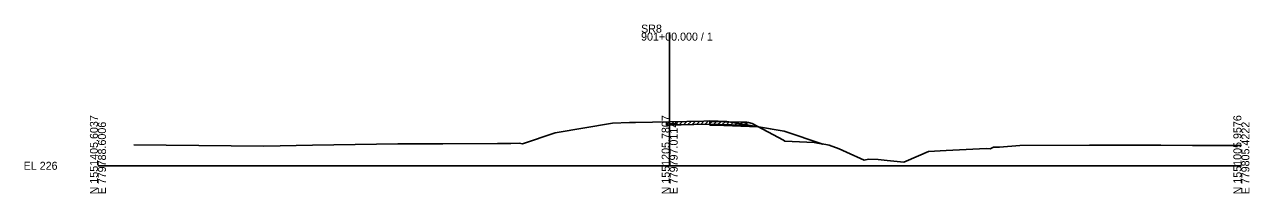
# Model space of a CAD drawing. Extents: x -26 to 787523, y -10 to 1545496.
# Drawn here: x -25.7 to 402.8, y 6990.3 to 7049.4 of the extents above; entities that cross this region are included whole.
import ezdxf

# ---------------------------------------------------------------- set-up
doc = ezdxf.new("R2010")
doc.units = 0
for name, color, linetype in [('50', 7, 'Continuous'), ('XS_CELL', 7, 'Continuous'), ('XS_M_SHAPES_EARTHWORK', 7, 'Continuous'), ('XS_P_FINISHED_GRADE', 7, 'Continuous'), ('XS_P_SUBGRADE_GRANULAR', 7, 'Continuous'), ('XS_X_GROUND', 7, 'Continuous')]:
    doc.layers.add(name, color=color, linetype=linetype)

msp = doc.modelspace()

# ---------------------------------------------------------------- linework, layer by layer
at = {"layer": '50'}
for p, q in [((198.85, 7014.25), (199.87, 7015.27)), ((198.85, 7014.25), (198.85, 7015.25)), ((200.36, 7014.28), (201.38, 7015.3)), ((201.86, 7014.31), (202.88, 7015.33)), ((203.36, 7014.34), (204.38, 7015.36)), ((204.86, 7014.37), (205.88, 7015.39)), ((206.36, 7014.4), (207.38, 7015.42)), ((207.87, 7014.43), (208.89, 7015.45)), ((209.37, 7014.46), (210.39, 7015.48)), ((210.87, 7014.49), (211.89, 7015.51)), ((212.37, 7014.51), (213.37, 7015.51)), ((213.87, 7014.5), (214.85, 7015.48)), ((215.38, 7014.47), (216.36, 7015.45)), ((216.88, 7014.44), (217.86, 7015.42)), ((218.38, 7014.4), (219.36, 7015.38)), ((219.88, 7014.37), (220.86, 7015.35)), ((221.38, 7014.34), (222.36, 7015.32)), ((222.89, 7014.31), (223.87, 7015.28)), ((224.39, 7014.27), (225.37, 7015.25)), ((225.89, 7014.24), (226.87, 7015.22)), ((227.04, 7015.21), (227.04, 7014.21)), ((198.85, 7014.25), (200, 7014.27)), ((200, 7014.27), (204, 7014.35)), ((204, 7014.35), (212.87, 7014.52)), ((212.87, 7014.52), (224.99, 7014.26)), ((224.99, 7014.26), (227.04, 7014.21))]:
    msp.add_line(p, q, dxfattribs=at)
at = {"layer": 'XS_CELL'}
for p, q in [((200, 7000), (200, 7046.57)), ((0, 7000), (200, 7000)), ((200, 7000), (400, 7000))]:
    msp.add_line(p, q, dxfattribs=at)
at = {"layer": 'XS_M_SHAPES_EARTHWORK'}
for points in [[(214, 7015.7), (214, 7015.5), (220.64, 7015.35), (220, 7015.46)], [(214, 7015.7), (214, 7015.5), (220.64, 7015.35), (220, 7015.46)], [(214, 7015.5), (220.64, 7015.35), (227.04, 7014.29), (227.04, 7014.21), (224.99, 7014.26), (214, 7014.5)], [(214, 7015.5), (220.64, 7015.35), (227.04, 7014.29), (227.04, 7014.21), (224.99, 7014.26), (214, 7014.5)], [(227.04, 7015.21), (227.04, 7014.29), (220.64, 7015.35), (224.99, 7015.26)], [(227.04, 7015.21), (227.04, 7014.29), (220.64, 7015.35), (224.99, 7015.26)], [(227.04, 7015.21), (227.04, 7014.29), (230.89, 7013.65), (231.03, 7013.62), (228.85, 7014.8), (227.56, 7015.09)], [(227.04, 7015.21), (227.04, 7014.29), (230.89, 7013.65), (231.03, 7013.62), (228.85, 7014.8), (227.56, 7015.09)], [(214, 7014.2), (214, 7014.5), (224.99, 7014.26), (227.04, 7014.21), (227.04, 7014.29), (230.89, 7013.65), (216, 7014.24)], [(214, 7014.2), (214, 7014.5), (224.99, 7014.26), (227.04, 7014.21), (227.04, 7014.29), (230.89, 7013.65), (216, 7014.24)], [(231.03, 7013.62), (240, 7012.13), (253.55, 7007.61), (250.6, 7008.19), (240.31, 7008.62), (239.77, 7008.91)], [(231.03, 7013.62), (240, 7012.13), (253.55, 7007.61), (250.6, 7008.19), (240.31, 7008.62), (239.77, 7008.91)]]:
    msp.add_lwpolyline(points, close=True, dxfattribs=at)
at = {"layer": 'XS_P_FINISHED_GRADE'}
for p, q in [((214, 7015.7), (220, 7015.46)), ((220, 7015.46), (240, 7012.13)), ((240, 7012.13), (253.55, 7007.61))]:
    msp.add_line(p, q, dxfattribs=at)
at = {"layer": 'XS_P_SUBGRADE_GRANULAR'}
for p, q in [((214, 7014.2), (214, 7015.7)), ((214, 7014.2), (216, 7014.24)), ((216, 7014.24), (230.89, 7013.65))]:
    msp.add_line(p, q, dxfattribs=at)
at = {"layer": 'XS_X_GROUND'}
for p, q in [((180, 7014.9), (186, 7015.14)), ((186, 7015.14), (188, 7015.18)), ((188, 7015.18), (200, 7015.42)), ((200, 7015.42), (212, 7015.66)), ((212, 7015.66), (214, 7015.7)), ((214, 7015.7), (214, 7015.5)), ((214, 7015.5), (224.99, 7015.26)), ((224.99, 7015.26), (227.04, 7015.21)), ((227.04, 7015.21), (227.56, 7015.09)), ((227.56, 7015.09), (228.85, 7014.8)), ((148.48, 7007.73), (160, 7011.57)), ((160, 7011.57), (180, 7014.9)), ((228.85, 7014.8), (239.77, 7008.91)), ((12.5, 7007.31), (23.9, 7007.22)), ((23.9, 7007.22), (58, 7006.9)), ((58, 7006.9), (75.01, 7007.18)), ((75.01, 7007.18), (104.89, 7007.69)), ((104.89, 7007.69), (108.24, 7007.67)), ((108.24, 7007.67), (116.38, 7007.65)), ((116.38, 7007.65), (120.7, 7007.63)), ((120.7, 7007.63), (139.81, 7007.74)), ((139.81, 7007.74), (141.47, 7007.78)), ((141.47, 7007.78), (144.43, 7007.85)), ((144.43, 7007.85), (147.38, 7007.92)), ((147.38, 7007.92), (148.48, 7007.73)), ((239.77, 7008.91), (240.31, 7008.62)), ((240.31, 7008.62), (250.6, 7008.19)), ((250.6, 7008.19), (254.67, 7007.39)), ((254.67, 7007.39), (255.83, 7007.17)), ((255.83, 7007.17), (259.24, 7005.93)), ((312.17, 7005.9), (313.23, 7006.54)), ((313.23, 7006.54), (315.4, 7006.54)), ((315.4, 7006.54), (322.51, 7007.13)), ((322.51, 7007.13), (346.9, 7007.17)), ((346.9, 7007.17), (352.31, 7007.17)), ((352.31, 7007.17), (362.64, 7007.18)), ((362.64, 7007.18), (371.79, 7007.18)), ((371.79, 7007.18), (382.95, 7007.12)), ((382.95, 7007.12), (395.37, 7007.1)), ((395.37, 7007.1), (400, 7007.08)), ((259.24, 7005.93), (261.84, 7004.76)), ((261.84, 7004.76), (267.99, 7002)), ((267.99, 7002), (269.61, 7002.28)), ((269.61, 7002.28), (272.92, 7002.23)), ((272.92, 7002.23), (276.06, 7001.87)), ((282.68, 7001.64), (290.55, 7005)), ((290.55, 7005), (296.68, 7005.31)), ((296.68, 7005.31), (310.74, 7006.08)), ((310.74, 7006.08), (312.17, 7005.9)), ((276.06, 7001.87), (281.88, 7001.25)), ((281.88, 7001.25), (282.68, 7001.64))]:
    msp.add_line(p, q, dxfattribs=at)

# ---------------------------------------------------------------- texts
at = {"layer": 'XS_CELL'}
for s, p in [('SR8', (190, 7046.57)), ('901+00.000 / 1', (190, 7043.77)), ('EL 226', (-26, 6998.6))]:
    msp.add_text(s, height=2.8, dxfattribs=at).set_placement(p)
for s, p in [('N 1551405.6037', (0, 6990)), ('E 779788.6006', (2.8, 6990)), ('N 1551205.7807', (200, 6990)), ('E 779797.0114', (202.8, 6990)), ('N 1551005.9576', (400, 6990)), ('E 779805.4222', (402.8, 6990))]:
    msp.add_text(s, height=2.8, rotation=90, dxfattribs=at).set_placement(p)

doc.saveas('drawing.dxf')
